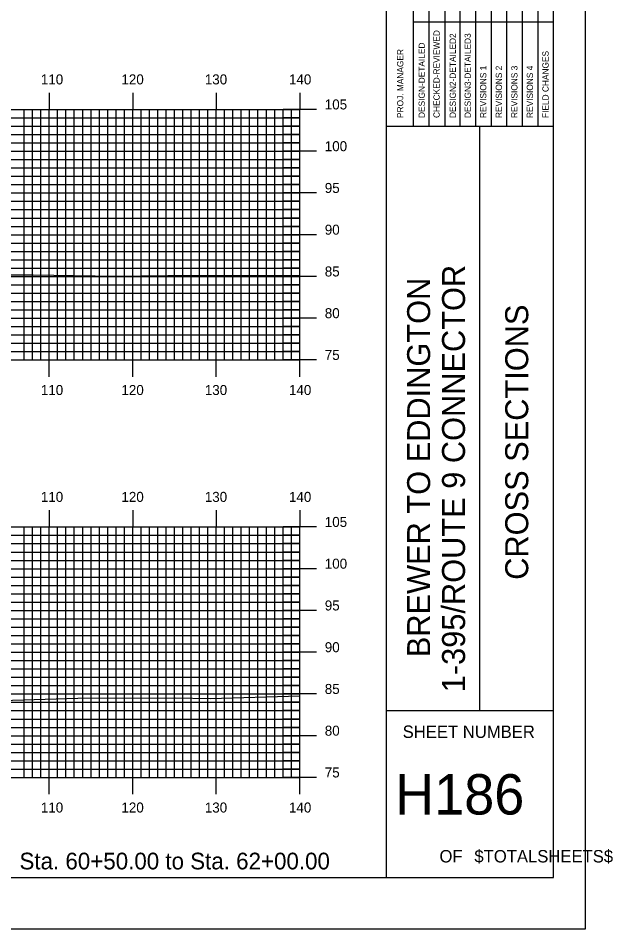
# Model space of a CAD drawing. Extents: x 1757856 to 1758199, y 442591 to 442811.
# Drawn here: x 1758127.9 to 1758199.1, y 442590.5 to 442699.6 of the extents above; entities that cross this region are included whole.
import ezdxf

# ---------------------------------------------------------------- set-up
doc = ezdxf.new("R2010")
doc.units = 0
for name, color, linetype in [('BORDER', 7, 'Continuous'), ('H_V ANNOTATION', 7, 'Continuous'), ('MAJOR', 7, 'Continuous'), ('MINOR', 7, 'Continuous'), ('PLOT BOUNDARY', 7, 'Continuous'), ('S_Roadway_Centerline', 7, 'Continuous')]:
    doc.layers.add(name, color=color, linetype=linetype)

msp = doc.modelspace()

# ---------------------------------------------------------------- linework, layer by layer
at = {"layer": 'BORDER'}
for p, q in [((1758172.02, 442596.67), (1758172.02, 442806.67)), ((1758172.02, 442686.67), (1758192.02, 442686.67)), ((1758183.2, 442616.67), (1758183.2, 442686.67)), ((1758172.02, 442616.67), (1758192.02, 442616.67))]:
    msp.add_line(p, q, dxfattribs=at)
msp.add_lwpolyline([(1757872.02, 442596.67), (1758192.02, 442596.67), (1758192.02, 442806.67), (1757872.02, 442806.67)], close=True, dxfattribs=at)
for points in [[(1758177.12, 442686.68), (1758177.12, 442721.67)], [(1758178.98, 442721.67), (1758178.98, 442686.68)], [(1758180.84, 442686.68), (1758180.84, 442721.67)], [(1758182.71, 442686.68), (1758182.71, 442721.67)], [(1758184.57, 442686.68), (1758184.57, 442721.67)], [(1758186.43, 442686.68), (1758186.43, 442721.67)], [(1758188.3, 442686.68), (1758188.3, 442721.67)], [(1758190.16, 442686.68), (1758190.16, 442721.67)], [(1758175.25, 442686.68), (1758175.25, 442720.26)], [(1758175.25, 442699.17), (1758192.02, 442699.17)]]:
    msp.add_lwpolyline(points, dxfattribs=at)
at = {"layer": 'MAJOR'}
for p, q in [((1758131.62, 442690.67), (1758131.62, 442688.67)), ((1758141.62, 442690.67), (1758141.62, 442688.67)), ((1758151.62, 442690.67), (1758151.62, 442688.67)), ((1758161.62, 442690.67), (1758161.62, 442688.67)), ((1757881.62, 442688.67), (1758161.62, 442688.67)), ((1757881.62, 442688.67), (1758161.62, 442688.67)), ((1758131.62, 442658.67), (1758131.62, 442688.67)), ((1758141.62, 442658.67), (1758141.62, 442688.67)), ((1758151.62, 442658.67), (1758151.62, 442688.67)), ((1758163.63, 442688.67), (1758159.62, 442688.67)), ((1758161.62, 442658.67), (1758161.62, 442688.67)), ((1758161.62, 442658.67), (1758161.62, 442688.67)), ((1757881.62, 442683.67), (1758161.62, 442683.67)), ((1758163.63, 442683.67), (1758159.62, 442683.67)), ((1757881.62, 442678.67), (1758161.62, 442678.67)), ((1758163.63, 442678.67), (1758159.62, 442678.67)), ((1757881.62, 442673.67), (1758161.62, 442673.67)), ((1758163.63, 442673.67), (1758159.62, 442673.67)), ((1757881.62, 442668.67), (1758161.62, 442668.67)), ((1758163.63, 442668.67), (1758159.62, 442668.67)), ((1757881.62, 442663.67), (1758161.62, 442663.67)), ((1758163.63, 442663.67), (1758159.62, 442663.67)), ((1757881.62, 442658.67), (1758161.62, 442658.67)), ((1757881.62, 442658.67), (1758161.62, 442658.67)), ((1758131.62, 442656.66), (1758131.62, 442658.67)), ((1758141.62, 442656.66), (1758141.62, 442658.67)), ((1758151.62, 442656.66), (1758151.62, 442658.67)), ((1758163.63, 442658.67), (1758159.62, 442658.67)), ((1758161.62, 442656.66), (1758161.62, 442658.67)), ((1758131.62, 442640.67), (1758131.62, 442638.67)), ((1758141.62, 442640.67), (1758141.62, 442638.67)), ((1758151.62, 442640.67), (1758151.62, 442638.67)), ((1758161.62, 442640.67), (1758161.62, 442638.67)), ((1757881.62, 442638.67), (1758161.62, 442638.67)), ((1757881.62, 442638.67), (1758161.62, 442638.67)), ((1758131.62, 442608.67), (1758131.62, 442638.67)), ((1758141.62, 442608.67), (1758141.62, 442638.67)), ((1758151.62, 442608.67), (1758151.62, 442638.67)), ((1758163.63, 442638.67), (1758159.62, 442638.67)), ((1758161.62, 442608.67), (1758161.62, 442638.67)), ((1758161.62, 442608.67), (1758161.62, 442638.67)), ((1757881.62, 442633.67), (1758161.62, 442633.67)), ((1758163.63, 442633.67), (1758159.62, 442633.67)), ((1757881.62, 442628.67), (1758161.62, 442628.67)), ((1758163.63, 442628.67), (1758159.62, 442628.67)), ((1757881.62, 442623.67), (1758161.62, 442623.67)), ((1758163.63, 442623.67), (1758159.62, 442623.67)), ((1757881.62, 442618.67), (1758161.62, 442618.67)), ((1758163.63, 442618.67), (1758159.62, 442618.67)), ((1757881.62, 442613.67), (1758161.62, 442613.67)), ((1758163.63, 442613.67), (1758159.62, 442613.67)), ((1757881.62, 442608.67), (1758161.62, 442608.67)), ((1757881.62, 442608.67), (1758161.62, 442608.67)), ((1758131.62, 442606.66), (1758131.62, 442608.67)), ((1758141.62, 442606.66), (1758141.62, 442608.67)), ((1758151.62, 442606.66), (1758151.62, 442608.67)), ((1758163.63, 442608.67), (1758159.62, 442608.67)), ((1758161.62, 442606.66), (1758161.62, 442608.67))]:
    msp.add_line(p, q, dxfattribs=at)
at = {"layer": 'MINOR'}
for p, q in [((1758128.62, 442658.67), (1758128.62, 442688.67)), ((1758129.62, 442658.67), (1758129.62, 442688.67)), ((1758130.62, 442658.67), (1758130.62, 442688.67)), ((1758132.62, 442658.67), (1758132.62, 442688.67)), ((1758133.62, 442658.67), (1758133.62, 442688.67)), ((1758134.62, 442658.67), (1758134.62, 442688.67)), ((1758135.62, 442658.67), (1758135.62, 442688.67)), ((1758136.62, 442658.67), (1758136.62, 442688.67)), ((1758137.62, 442658.67), (1758137.62, 442688.67)), ((1758138.62, 442658.67), (1758138.62, 442688.67)), ((1758139.62, 442658.67), (1758139.62, 442688.67)), ((1758140.62, 442658.67), (1758140.62, 442688.67)), ((1758142.62, 442658.67), (1758142.62, 442688.67)), ((1758143.62, 442658.67), (1758143.62, 442688.67)), ((1758144.62, 442658.67), (1758144.62, 442688.67)), ((1758145.62, 442658.67), (1758145.62, 442688.67)), ((1758146.62, 442658.67), (1758146.62, 442688.67)), ((1758147.62, 442658.67), (1758147.62, 442688.67)), ((1758148.62, 442658.67), (1758148.62, 442688.67)), ((1758149.62, 442658.67), (1758149.62, 442688.67)), ((1758150.62, 442658.67), (1758150.62, 442688.67)), ((1758152.62, 442658.67), (1758152.62, 442688.67)), ((1758153.62, 442658.67), (1758153.62, 442688.67)), ((1758154.62, 442658.67), (1758154.62, 442688.67)), ((1758155.62, 442658.67), (1758155.62, 442688.67)), ((1758156.62, 442658.67), (1758156.62, 442688.67)), ((1758157.62, 442658.67), (1758157.62, 442688.67)), ((1758158.62, 442658.67), (1758158.62, 442688.67)), ((1758159.62, 442658.67), (1758159.62, 442688.67)), ((1758160.62, 442658.67), (1758160.62, 442688.67)), ((1757881.62, 442687.67), (1758161.62, 442687.67)), ((1758161.62, 442687.67), (1758159.62, 442687.67)), ((1757881.62, 442686.67), (1758161.62, 442686.67)), ((1758161.62, 442686.67), (1758159.62, 442686.67)), ((1757881.62, 442685.67), (1758161.62, 442685.67)), ((1758161.62, 442685.67), (1758159.62, 442685.67)), ((1757881.62, 442684.67), (1758161.62, 442684.67)), ((1758161.62, 442684.67), (1758159.62, 442684.67)), ((1757881.62, 442682.67), (1758161.62, 442682.67)), ((1758161.62, 442682.67), (1758159.62, 442682.67)), ((1757881.62, 442681.67), (1758161.62, 442681.67)), ((1758161.62, 442681.67), (1758159.62, 442681.67)), ((1757881.62, 442680.67), (1758161.62, 442680.67)), ((1757881.62, 442679.67), (1758161.62, 442679.67)), ((1758161.62, 442680.67), (1758159.62, 442680.67)), ((1758161.62, 442679.67), (1758159.62, 442679.67)), ((1757881.62, 442677.67), (1758161.62, 442677.67)), ((1758161.62, 442677.67), (1758159.62, 442677.67)), ((1757881.62, 442676.67), (1758161.62, 442676.67)), ((1758161.62, 442676.67), (1758159.62, 442676.67)), ((1757881.62, 442675.67), (1758161.62, 442675.67)), ((1758161.62, 442675.67), (1758159.62, 442675.67)), ((1757881.62, 442674.67), (1758161.62, 442674.67)), ((1758161.62, 442674.67), (1758159.62, 442674.67)), ((1757881.62, 442672.67), (1758161.62, 442672.67)), ((1758161.62, 442672.67), (1758159.62, 442672.67)), ((1757881.62, 442671.67), (1758161.62, 442671.67)), ((1758161.62, 442671.67), (1758159.62, 442671.67)), ((1757881.62, 442670.67), (1758161.62, 442670.67)), ((1758161.62, 442670.67), (1758159.62, 442670.67)), ((1757881.62, 442669.67), (1758161.62, 442669.67)), ((1758161.62, 442669.67), (1758159.62, 442669.67)), ((1757881.62, 442667.67), (1758161.62, 442667.67)), ((1758161.62, 442667.67), (1758159.62, 442667.67)), ((1757881.62, 442666.67), (1758161.62, 442666.67)), ((1758161.62, 442666.67), (1758159.62, 442666.67)), ((1757881.62, 442665.67), (1758161.62, 442665.67)), ((1758161.62, 442665.67), (1758159.62, 442665.67)), ((1757881.62, 442664.67), (1758161.62, 442664.67)), ((1758161.62, 442664.67), (1758159.62, 442664.67)), ((1757881.62, 442662.67), (1758161.62, 442662.67)), ((1758161.62, 442662.67), (1758159.62, 442662.67)), ((1757881.62, 442661.67), (1758161.62, 442661.67)), ((1758161.62, 442661.67), (1758159.62, 442661.67)), ((1757881.62, 442660.67), (1758161.62, 442660.67)), ((1758161.62, 442660.67), (1758159.62, 442660.67)), ((1757881.62, 442659.67), (1758161.62, 442659.67)), ((1758161.62, 442659.67), (1758159.62, 442659.67)), ((1758128.62, 442608.67), (1758128.62, 442638.67)), ((1758129.62, 442608.67), (1758129.62, 442638.67)), ((1758130.62, 442608.67), (1758130.62, 442638.67)), ((1758132.62, 442608.67), (1758132.62, 442638.67)), ((1758133.62, 442608.67), (1758133.62, 442638.67)), ((1758134.62, 442608.67), (1758134.62, 442638.67)), ((1758135.62, 442608.67), (1758135.62, 442638.67)), ((1758136.62, 442608.67), (1758136.62, 442638.67)), ((1758137.62, 442608.67), (1758137.62, 442638.67)), ((1758138.62, 442608.67), (1758138.62, 442638.67)), ((1758139.62, 442608.67), (1758139.62, 442638.67)), ((1758140.62, 442608.67), (1758140.62, 442638.67)), ((1758142.62, 442608.67), (1758142.62, 442638.67)), ((1758143.62, 442608.67), (1758143.62, 442638.67)), ((1758144.62, 442608.67), (1758144.62, 442638.67)), ((1758145.62, 442608.67), (1758145.62, 442638.67)), ((1758146.62, 442608.67), (1758146.62, 442638.67)), ((1758147.62, 442608.67), (1758147.62, 442638.67)), ((1758148.62, 442608.67), (1758148.62, 442638.67)), ((1758149.62, 442608.67), (1758149.62, 442638.67)), ((1758150.62, 442608.67), (1758150.62, 442638.67)), ((1758152.62, 442608.67), (1758152.62, 442638.67)), ((1758153.62, 442608.67), (1758153.62, 442638.67)), ((1758154.62, 442608.67), (1758154.62, 442638.67)), ((1758155.62, 442608.67), (1758155.62, 442638.67)), ((1758156.62, 442608.67), (1758156.62, 442638.67)), ((1758157.62, 442608.67), (1758157.62, 442638.67)), ((1758158.62, 442608.67), (1758158.62, 442638.67)), ((1758159.62, 442608.67), (1758159.62, 442638.67)), ((1758160.62, 442608.67), (1758160.62, 442638.67)), ((1757881.62, 442637.67), (1758161.62, 442637.67)), ((1758161.62, 442637.67), (1758159.62, 442637.67)), ((1757881.62, 442636.67), (1758161.62, 442636.67)), ((1758161.62, 442636.67), (1758159.62, 442636.67)), ((1757881.62, 442635.67), (1758161.62, 442635.67)), ((1758161.62, 442635.67), (1758159.62, 442635.67)), ((1757881.62, 442634.67), (1758161.62, 442634.67)), ((1758161.62, 442634.67), (1758159.62, 442634.67)), ((1757881.62, 442632.67), (1758161.62, 442632.67)), ((1758161.62, 442632.67), (1758159.62, 442632.67)), ((1757881.62, 442631.67), (1758161.62, 442631.67)), ((1757881.62, 442630.67), (1758161.62, 442630.67)), ((1758161.62, 442631.67), (1758159.62, 442631.67)), ((1758161.62, 442630.67), (1758159.62, 442630.67)), ((1757881.62, 442629.67), (1758161.62, 442629.67)), ((1758161.62, 442629.67), (1758159.62, 442629.67)), ((1757881.62, 442627.67), (1758161.62, 442627.67)), ((1758161.62, 442627.67), (1758159.62, 442627.67)), ((1757881.62, 442626.67), (1758161.62, 442626.67)), ((1758161.62, 442626.67), (1758159.62, 442626.67)), ((1757881.62, 442625.67), (1758161.62, 442625.67)), ((1758161.62, 442625.67), (1758159.62, 442625.67)), ((1757881.62, 442624.67), (1758161.62, 442624.67)), ((1758161.62, 442624.67), (1758159.62, 442624.67)), ((1757881.62, 442622.67), (1758161.62, 442622.67)), ((1758161.62, 442622.67), (1758159.62, 442622.67)), ((1757881.62, 442621.67), (1758161.62, 442621.67)), ((1758161.62, 442621.67), (1758159.62, 442621.67)), ((1757881.62, 442620.67), (1758161.62, 442620.67)), ((1758161.62, 442620.67), (1758159.62, 442620.67)), ((1757881.62, 442619.67), (1758161.62, 442619.67)), ((1758161.62, 442619.67), (1758159.62, 442619.67)), ((1757881.62, 442617.67), (1758161.62, 442617.67)), ((1758161.62, 442617.67), (1758159.62, 442617.67)), ((1757881.62, 442616.67), (1758161.62, 442616.67)), ((1758161.62, 442616.67), (1758159.62, 442616.67)), ((1757881.62, 442615.67), (1758161.62, 442615.67)), ((1758161.62, 442615.67), (1758159.62, 442615.67)), ((1757881.62, 442614.67), (1758161.62, 442614.67)), ((1758161.62, 442614.67), (1758159.62, 442614.67)), ((1757881.62, 442612.67), (1758161.62, 442612.67)), ((1758161.62, 442612.67), (1758159.62, 442612.67)), ((1757881.62, 442611.67), (1758161.62, 442611.67)), ((1758161.62, 442611.67), (1758159.62, 442611.67)), ((1757881.62, 442610.67), (1758161.62, 442610.67)), ((1758161.62, 442610.67), (1758159.62, 442610.67)), ((1757881.62, 442609.67), (1758161.62, 442609.67)), ((1758161.62, 442609.67), (1758159.62, 442609.67))]:
    msp.add_line(p, q, dxfattribs=at)
at = {"layer": 'PLOT BOUNDARY'}
msp.add_lwpolyline([(1757855.84, 442590.55), (1758195.84, 442590.55), (1758195.84, 442810.55), (1757855.84, 442810.55)], close=True, dxfattribs=at)
at = {"layer": 'S_Roadway_Centerline'}
for points in [[(1758080.06, 442668.24), (1758097.4, 442668.75), (1758103.71, 442668.85), (1758107.75, 442668.96), (1758116.17, 442668.84), (1758126.78, 442668.88), (1758129.7, 442668.86), (1758139.58, 442668.71), (1758145.82, 442668.77), (1758159.27, 442668.79), (1758161.62, 442668.79)], [(1758077.01, 442617.74), (1758084.81, 442617.57), (1758096.94, 442617.36), (1758116.11, 442617.6), (1758116.52, 442617.61), (1758116.62, 442617.61), (1758116.75, 442617.61), (1758135.04, 442618.18), (1758146.69, 442618.22), (1758150.89, 442618.14), (1758161.62, 442618.43)]]:
    msp.add_lwpolyline(points, dxfattribs=at)

# ---------------------------------------------------------------- texts
at = {"layer": 'BORDER'}
for s, height, p in [('CHECKED-REVIEWED', 0.7455, (1758178.38, 442687.65)), ('DESIGN2-DETAILED2', 0.7455, (1758180.32, 442687.65)), ('DESIGN3-DETAILED3', 0.7455, (1758182.11, 442687.65)), ('DESIGN-DETAILED', 0.7455, (1758176.6, 442687.65)), ('PROJ. MANAGER', 0.7455, (1758174.03, 442687.65)), ('FIELD CHANGES', 0.7455, (1758191.43, 442687.65)), ('REVISIONS 1', 0.7455, (1758183.97, 442687.65)), ('REVISIONS 2', 0.7455, (1758185.84, 442687.65)), ('REVISIONS 3', 0.7455, (1758187.7, 442687.65)), ('REVISIONS 4', 0.7455, (1758189.56, 442687.65)), ('1-395/ROUTE 9 CONNECTOR', 2.7557, (1758181.42, 442618.87)), ('BREWER TO EDDINGTON', 2.7557, (1758177.24, 442623.07)), ('CROSS SECTIONS', 2.7557, (1758188.99, 442632.34))]:
    msp.add_text(s, height=height, rotation=90, dxfattribs=at).set_placement(p)
for s, height, p in [('SHEET NUMBER', 1.4905, (1758173.95, 442613.4)), ('H186', 4.839, (1758173.05, 442604.23)), ('$TOTALSHEETS$', 1.4905, (1758182.54, 442598.49)), ('OF', 1.491, (1758178.36, 442598.49))]:
    msp.add_text(s, height=height, dxfattribs=at).set_placement(p)
at = {"layer": 'H_V ANNOTATION'}
for s, height, p in [('110', 1.2, (1758130.61, 442691.67)), ('120', 1.2, (1758140.26, 442691.67)), ('130', 1.2, (1758150.25, 442691.67)), ('140', 1.2, (1758160.33, 442691.67)), ('105', 1.2, (1758164.62, 442688.67)), ('100', 1.2, (1758164.62, 442683.67)), ('95', 1.2, (1758164.62, 442678.67)), ('90', 1.2, (1758164.62, 442673.67)), ('85', 1.2, (1758164.62, 442668.67)), ('80', 1.2, (1758164.62, 442663.67)), ('75', 1.2, (1758164.62, 442658.67)), ('110', 1.2, (1758130.61, 442654.47)), ('120', 1.2, (1758140.26, 442654.47)), ('130', 1.2, (1758150.25, 442654.47)), ('140', 1.2, (1758160.33, 442654.47)), ('110', 1.2, (1758130.61, 442641.67)), ('120', 1.2, (1758140.26, 442641.67)), ('130', 1.2, (1758150.25, 442641.67)), ('140', 1.2, (1758160.33, 442641.67)), ('105', 1.2, (1758164.62, 442638.67)), ('100', 1.2, (1758164.62, 442633.67)), ('95', 1.2, (1758164.62, 442628.67)), ('90', 1.2, (1758164.62, 442623.67)), ('85', 1.2, (1758164.62, 442618.67)), ('80', 1.2, (1758164.62, 442613.67)), ('75', 1.2, (1758164.62, 442608.67)), ('110', 1.2, (1758130.61, 442604.47)), ('120', 1.2, (1758140.26, 442604.47)), ('130', 1.2, (1758150.25, 442604.47)), ('140', 1.2, (1758160.33, 442604.47)), ('Sta. 60+50.00 to Sta. 62+00.00', 2.0004, (1758128.05, 442597.66))]:
    msp.add_text(s, height=height, dxfattribs=at).set_placement(p)

doc.saveas('drawing.dxf')
